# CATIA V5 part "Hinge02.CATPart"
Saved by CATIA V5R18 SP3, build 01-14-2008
Part number: Hinge 02
Bounding box of the stored display mesh (mm): x -47.5 to 47.5, y -15 to 15, z -14 to 14
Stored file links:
  E:\#00 CATIA V5 Movie\#03 CATIA V5 Data\#07 KIN\Balance Unit (1)\Hinge02.CATPart
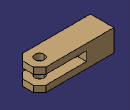
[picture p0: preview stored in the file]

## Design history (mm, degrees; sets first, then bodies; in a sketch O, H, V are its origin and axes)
Body1 (main body)
  Sketch1 on xy-plane, origin (0, 0, 0), H (1, 0, 0), V (0, 1, 0)
    line L1 (47.5, 7) -> (47.5, -7)
    line L2 (39.5, -15) -> (-47.5, -15)
    line L3 (-47.5, -15) -> (-47.5, 15)
    line L4 (-47.5, 15) -> (39.5, 15)
    point P1 (47.5, 15)
    point P2 (47.5, -15)
    point P4 (-47.5, 15)
    line L5 (47.5, 7) -> (39.5, 15)
    point P5 (47.5, 7)
    point P6 (39.5, 15)
    line L6 (47.5, -7) -> (39.5, -15)
    point P7 (47.5, -7)
    point P8 (39.5, -15)
    circle A1 centre (32.5, 0) radius 6
    point P9 (32.5, 0)
    distance P1 P2 = 30
    distance P4 P1 = 95
    distance P5 P1 = 8
    distance P6 P1 = 8
    distance P7 P2 = 8 {= Sketch1.distance(P5 P1)}
    distance P8 P2 = 8 {= Sketch1.distance(P6 P1)}
    distance P9 L3 = 80
    radius A1 = 6
    vertical: L1 V, L3 V
    horizontal: L2 H, L4 H
    equidistance: L1 L3 O, L2 L4 O
    coincidence: L1 P1, L4 P1, L1 P2, L2 P2, P9 H
  Pad1: profile Sketch1, direction (0, 0, 1), length 14, mirrored extent
  Sketch2 on face of Pad1 from Sketch1.L2, origin (0, -15, 0), H (1, 0, 0), V (0, 0, 1)
    line L1 (47.5, 6) -> (-12.5, 6)
    line L2 (-12.5, 6) -> (-12.5, -6)
    line L3 (-12.5, -6) -> (47.5, -6)
    line L4 (47.5, -6) -> (47.5, 6)
    reference intersected line E1 through (47.5, 0) direction (0, -1) from face of Pad1 from Sketch1.L1
    length L3 = 60
    distance L1 L3 = 12
    horizontal: L1 H, L3 H
    vertical: L2 V, L4 V
    coincidence: L4 E1
    symmetry: L1 L3 H
  Pocket1: profile Sketch2, direction (0, 1, 0), through (limit type 6)
  Sketch3 on face of Pad1 from Sketch1.L3, origin (-47.5, 0, 0), H (0, 1, 0), V (0, 0, -1)
    point P1 (0, 0)
    reference projected point E1 (0, 0) from Sketch4.P1
    coincidence: E1 P1
  Hole1: placed by Sketch3, at (-47.5, 0, 0) direction (1, 0, 0), diameter 13.835, depth 37, V-bottom angle 120, threaded "M16", thread diameter 16, thread depth 35, pitch 2
  Sketch4 on face of Pad1 from Sketch1.L3, origin (-47.5, 0, 0), H (0, -1, 0), V (0, 0, 1)
    point P1 (0, 0)
    coincidence: P1 O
